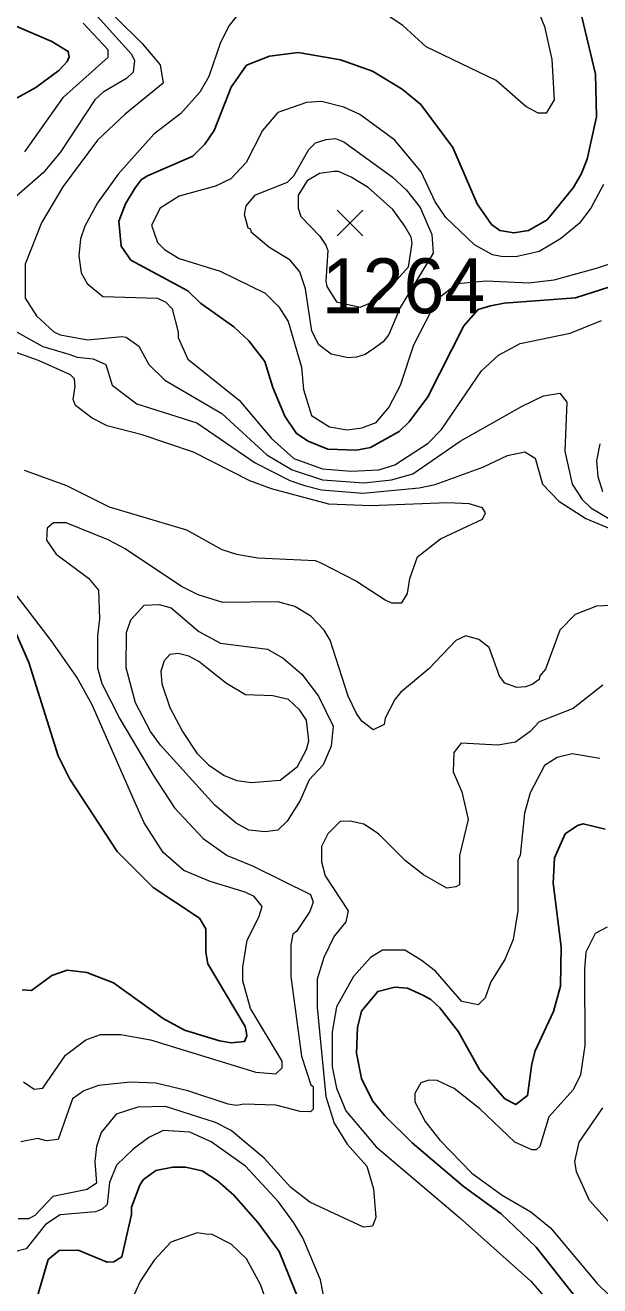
# Model space of a CAD drawing. Extents: x 423 to 448.8, y 7456.3 to 7484.
# Drawn here: x 429.568 to 430.405, y 7470.972 to 7472.809 of the extents above; entities that cross this region are included whole.
import ezdxf
from ezdxf.enums import TextEntityAlignment as Align

# ---------------------------------------------------------------- set-up
doc = ezdxf.new("R2010")
doc.units = 0
doc.header["$LTSCALE"] = 0.032
for name, color, linetype, lineweight in [('1', 7, 'Continuous', 25), ('2', 7, 'Continuous', 13), ('21', 7, 'Continuous', 25)]:
    doc.layers.add(name, color=color, linetype=linetype, lineweight=lineweight)
doc.layers.add('61', color=7, linetype='Continuous')

msp = doc.modelspace()

# ---------------------------------------------------------------- linework, layer by layer
at = {"layer": '1'}
for points in [[(429.5559, 7472.8071), (429.6069, 7472.7854), (429.6309, 7472.7707), (429.6324, 7472.763), (429.6294, 7472.756), (429.617, 7472.7428), (429.5837, 7472.7181), (429.5157, 7472.681)], [(430.1909, 7472.6307), (430.2265, 7472.5487), (430.2473, 7472.5186), (430.2597, 7472.51), (430.2799, 7472.5062), (430.3015, 7472.51), (430.3286, 7472.5255), (430.3665, 7472.5719), (430.3781, 7472.592), (430.3866, 7472.6137), (430.4005, 7472.6756), (430.399, 7472.7375), (430.3788, 7472.821)], [(430.532, 7472.4636), (430.3696, 7472.4118), (430.2659, 7472.4041), (430.2458, 7472.4002), (430.228, 7472.3948), (430.2071, 7472.3708), (430.1545, 7472.2672), (430.1274, 7472.2308), (430.1128, 7472.2169), (430.071, 7472.1937), (430.0509, 7472.1898), (430.0091, 7472.1914), (429.9805, 7472.203), (429.9635, 7472.2138), (429.9465, 7472.2394), (429.9287, 7472.2811), (429.9171, 7472.319), (429.8939, 7472.3492), (429.8722, 7472.3693), (429.8235, 7472.4041), (429.805, 7472.4219), (429.7222, 7472.4667), (429.7082, 7472.4869), (429.7044, 7472.5232), (429.7144, 7472.5487), (429.7283, 7472.5719), (429.7376, 7472.5843), (429.7462, 7472.5897), (429.8126, 7472.6183), (429.8297, 7472.6354), (429.8436, 7472.6555), (429.8684, 7472.7189), (429.8908, 7472.7506), (429.9241, 7472.7637), (429.9658, 7472.7692), (430.0277, 7472.7583), (430.0741, 7472.7421), (430.1174, 7472.7158), (430.1445, 7472.6933), (430.1909, 7472.6307)], [(429.5512, 7471.9315), (429.5737, 7471.8805), (429.6162, 7471.7443), (429.6332, 7471.7103), (429.702, 7471.6051), (429.7547, 7471.5525), (429.8219, 7471.5076), (429.8312, 7471.4922), (429.8312, 7471.4582), (429.8343, 7471.4411), (429.8885, 7471.3499), (429.89, 7471.3429), (429.891, 7471.3362), (429.8877, 7471.3282), (429.8684, 7471.3259), (429.8514, 7471.329), (429.8003, 7471.3444), (429.7694, 7471.3614), (429.6966, 7471.4133), (429.658, 7471.4288), (429.6294, 7471.4318), (429.6069, 7471.4241), (429.5776, 7471.4024), (429.5636, 7471.4032)], [(430.0919, 7471.2199), (430.0741, 7471.2416), (430.0579, 7471.2741), (430.0509, 7471.3112), (430.0524, 7471.3483), (430.0579, 7471.3723), (430.0818, 7471.4009), (430.1066, 7471.4071), (430.1252, 7471.4055), (430.1476, 7471.3955), (430.1592, 7471.3893), (430.1723, 7471.3769), (430.1994, 7471.3421), (430.2303, 7471.2864), (430.2667, 7471.2447), (430.2829, 7471.2361), (430.2999, 7471.2493), (430.3061, 7471.2957), (430.3108, 7471.3143), (430.3378, 7471.3715), (430.3479, 7471.4087), (430.3487, 7471.4659), (430.3371, 7471.5587), (430.3394, 7471.5958), (430.3549, 7471.6306), (430.3727, 7471.643), (430.3811, 7471.6453), (430.4129, 7471.6376)], [(430.3904, 7470.9299), (430.3123, 7471.0281), (430.2613, 7471.0768), (430.2063, 7471.117), (430.1321, 7471.1804), (430.0919, 7471.2199)], [(429.5845, 7470.9523), (429.6015, 7471.0103), (429.6178, 7471.0235), (429.6456, 7471.0242), (429.6874, 7471.0064), (429.6974, 7471.0072), (429.709, 7471.0141), (429.723, 7471.0761), (429.723, 7471.0868), (429.7353, 7471.1186), (429.7381, 7471.1237), (429.7407, 7471.1271), (429.7585, 7471.1402), (429.7833, 7471.1449), (429.8019, 7471.1449), (429.8258, 7471.1395), (429.8483, 7471.1248), (429.8722, 7471.1039), (429.9078, 7471.0637), (429.938, 7471.0219), (429.9681, 7470.9477)]]:
    msp.add_lwpolyline(points, dxfattribs=at)
at = {"layer": '2'}
for points in [[(430.2969, 7472.8751), (430.3247, 7472.8071), (430.3355, 7472.7591), (430.3386, 7472.7003), (430.327, 7472.681), (430.3154, 7472.681), (430.2976, 7472.6903), (430.2543, 7472.7282), (430.1522, 7472.7776), (430.1182, 7472.8086), (430.0865, 7472.8295)], [(429.6626, 7472.8581), (429.7384, 7472.7823), (429.7647, 7472.7514), (429.7694, 7472.7243), (429.7137, 7472.6794), (429.6734, 7472.6415), (429.6232, 7472.5735), (429.5922, 7472.5209), (429.5683, 7472.4606), (429.5683, 7472.4111), (429.5845, 7472.3855), (429.61, 7472.3623), (429.6193, 7472.3577), (429.6595, 7472.3507), (429.709, 7472.3554), (429.7152, 7472.3546), (429.7338, 7472.3414), (429.7485, 7472.3143), (429.7717, 7472.2919), (429.8544, 7472.2432), (429.9202, 7472.1829), (429.9573, 7472.1612), (430.0014, 7472.1465), (430.0617, 7472.1419), (430.102, 7472.1465), (430.1329, 7472.155), (430.2017, 7472.203), (430.2922, 7472.254), (430.3232, 7472.2687), (430.3471, 7472.2726), (430.3572, 7472.2595), (430.3541, 7472.1883), (430.3649, 7472.1403), (430.3796, 7472.1179), (430.392, 7472.1055), (430.4183, 7472.09)], [(429.6688, 7472.8272), (429.7229, 7472.7668), (429.7276, 7472.7576), (429.7253, 7472.7405), (429.716, 7472.7313), (429.6819, 7472.7112), (429.6696, 7472.7003), (429.6193, 7472.6237), (429.5946, 7472.5936)], [(429.8854, 7472.8333), (429.8653, 7472.8086), (429.8529, 7472.7839), (429.8359, 7472.7344), (429.8227, 7472.7112), (429.7949, 7472.6802), (429.7554, 7472.65), (429.7036, 7472.592), (429.6735, 7472.5503), (429.6549, 7472.5162), (429.6487, 7472.4977), (429.6464, 7472.4729), (429.6495, 7472.4482), (429.6587, 7472.4327), (429.6812, 7472.4134), (429.7608, 7472.4111), (429.7732, 7472.4056), (429.7825, 7472.3956), (429.791, 7472.3616), (429.791, 7472.3538), (429.8049, 7472.3221), (429.88, 7472.2625), (429.9271, 7472.2069), (429.9596, 7472.1774), (430.0014, 7472.1627), (430.0432, 7472.1589), (430.0834, 7472.1612), (430.1066, 7472.1682), (430.1553, 7472.1999), (430.1747, 7472.22), (430.2327, 7472.3051), (430.2574, 7472.3283), (430.2891, 7472.3453), (430.3618, 7472.36), (430.4075, 7472.3786)], [(429.5675, 7472.6245), (429.624, 7472.7042), (429.6889, 7472.7622), (429.6889, 7472.773), (429.6526, 7472.8117)], [(430.4105, 7472.5766), (430.392, 7472.5425), (430.375, 7472.5201), (430.3479, 7472.4976), (430.317, 7472.4791), (430.283, 7472.4714), (430.2613, 7472.4721), (430.2489, 7472.4745), (430.2226, 7472.4891), (430.1808, 7472.5286), (430.1653, 7472.5518), (430.1452, 7472.5951), (430.1066, 7472.6415), (430.0556, 7472.6787), (430.0324, 7472.6895), (429.9999, 7472.698), (429.9782, 7472.6964), (429.9364, 7472.6818), (429.914, 7472.6555), (429.89, 7472.609), (429.8676, 7472.5851), (429.8452, 7472.5742), (429.7926, 7472.5596), (429.7647, 7472.5425), (429.7524, 7472.5178), (429.7608, 7472.4922), (429.7709, 7472.4822), (429.7926, 7472.469), (429.8521, 7472.4505), (429.9178, 7472.4187), (429.9379, 7472.3987), (429.9511, 7472.377), (429.9705, 7472.3105), (429.9736, 7472.278), (429.9851, 7472.2401), (430.0114, 7472.2238), (430.037, 7472.2192), (430.0586, 7472.2223), (430.0795, 7472.23), (430.0981, 7472.2517), (430.1151, 7472.2842), (430.1344, 7472.343), (430.169, 7472.41), (430.1976, 7472.4325), (430.2396, 7472.4366), (430.3015, 7472.4335), (430.3386, 7472.4381), (430.4005, 7472.4551), (430.5188, 7472.4938)], [(429.5946, 7472.5936), (429.5218, 7472.5309)], [(429.5512, 7472.3646), (429.5938, 7472.3406), (429.6317, 7472.3298), (429.6441, 7472.3252), (429.6673, 7472.3229), (429.6858, 7472.3144), (429.6951, 7472.2842), (429.7307, 7472.2571), (429.8181, 7472.2293), (429.9032, 7472.1712), (429.9535, 7472.1457), (429.9751, 7472.138), (429.9999, 7472.1318), (430.0602, 7472.1272), (430.1422, 7472.1349), (430.1654, 7472.1395), (430.235, 7472.1651), (430.2706, 7472.1821), (430.2961, 7472.1875), (430.3108, 7472.1782), (430.3216, 7472.1403), (430.3456, 7472.1156), (430.385, 7472.09), (430.4686, 7472.0553)], [(429.6286, 7472.138), (429.6905, 7472.1071), (429.8034, 7472.0738), (429.8545, 7472.0452), (429.8761, 7472.0382), (429.9071, 7472.0328), (429.9906, 7472.029), (429.9999, 7472.0251), (430.0509, 7471.9988), (430.0927, 7471.9717), (430.102, 7471.9671), (430.1166, 7471.9671), (430.1252, 7471.981), (430.1283, 7472.0027), (430.1398, 7472.0344), (430.1731, 7472.0606), (430.2342, 7472.0893), (430.2388, 7472.0986), (430.2342, 7472.1055), (430.2149, 7472.1117), (430.1839, 7472.1132), (430.071, 7472.1086), (430.0107, 7472.1109), (429.9272, 7472.1334), (429.8954, 7472.145), (429.8134, 7472.1867), (429.7384, 7472.2122), (429.6874, 7472.2254), (429.6657, 7472.2363), (429.6417, 7472.2548), (429.6379, 7472.2633), (429.641, 7472.2827), (429.6402, 7472.2935), (429.634, 7472.2997), (429.5876, 7472.3205), (429.5234, 7472.343)], [(430.4052, 7472.1991), (430.4005, 7472.1744), (430.4021, 7472.1512), (430.409, 7472.1295)], [(429.5667, 7472.1605), (429.6286, 7472.138)], [(429.7137, 7472.0459), (429.6889, 7472.0591), (429.6278, 7472.0839), (429.6092, 7472.0839), (429.6, 7472.0761), (429.5992, 7472.0584), (429.6131, 7472.0382), (429.6603, 7472.0034), (429.675, 7471.9857), (429.6766, 7471.9439), (429.6735, 7471.9191), (429.6735, 7471.8727), (429.6796, 7471.8495), (429.7059, 7471.7984), (429.7554, 7471.7149), (429.7856, 7471.6685), (429.8274, 7471.6237), (429.8622, 7471.5989), (429.8993, 7471.5842), (429.9836, 7471.5424), (429.9875, 7471.5309), (429.9828, 7471.5177), (429.9635, 7471.4883), (429.9581, 7471.4845), (429.955, 7471.469), (429.955, 7471.4226), (429.9705, 7471.3066), (429.9844, 7471.2648), (429.9875, 7471.2624), (429.9875, 7471.2292), (429.9836, 7471.2253), (429.9689, 7471.2261), (429.9333, 7471.2354), (429.8869, 7471.2369), (429.8761, 7471.2346), (429.8637, 7471.2369), (429.805, 7471.2562), (429.7585, 7471.2671), (429.7214, 7471.2686), (429.675, 7471.264), (429.6534, 7471.2562), (429.6371, 7471.2447), (429.6162, 7471.1851), (429.5992, 7471.1835), (429.5868, 7471.1866), (429.562, 7471.182)], [(429.5659, 7471.2694), (429.5814, 7471.2586), (429.5938, 7471.2601), (429.6271, 7471.3081), (429.6564, 7471.3305), (429.6781, 7471.3382), (429.7075, 7471.3382), (429.7508, 7471.3305), (429.904, 7471.2833), (429.9333, 7471.281), (429.9426, 7471.2895), (429.9426, 7471.2996), (429.8962, 7471.3762), (429.8854, 7471.4164), (429.8854, 7471.4365), (429.8916, 7471.4759), (429.9086, 7471.5092), (429.9132, 7471.5247), (429.9016, 7471.5393), (429.8885, 7471.5455), (429.8374, 7471.561), (429.7995, 7471.5773), (429.7693, 7471.6036), (429.7415, 7471.6469), (429.7268, 7471.6794), (429.6657, 7471.8186), (429.6433, 7471.8588), (429.6061, 7471.9122), (429.5041, 7472.0452)], [(430.4206, 7471.9632), (430.4005, 7471.9624), (430.3695, 7471.9501), (430.3471, 7471.9276), (430.3262, 7471.8704), (430.3177, 7471.8611), (430.3169, 7471.8557), (430.3069, 7471.848), (430.2969, 7471.8449), (430.2845, 7471.8441), (430.2667, 7471.8503), (430.2589, 7471.8604), (430.2442, 7471.9021), (430.2288, 7471.9137), (430.2102, 7471.9191), (430.1955, 7471.9122), (430.1561, 7471.8712), (430.1151, 7471.8364), (430.1066, 7471.8263), (430.0927, 7471.7992), (430.0911, 7471.7899), (430.0749, 7471.7822), (430.0586, 7471.7946), (430.0509, 7471.8062), (430.0385, 7471.831), (430.0122, 7471.913), (430.0037, 7471.9276), (429.9844, 7471.9477), (429.9612, 7471.9617), (429.9364, 7471.9686), (429.856, 7471.9678), (429.8204, 7471.9787), (429.7957, 7471.991), (429.7137, 7472.0459)], [(430.4098, 7471.8472), (430.3665, 7471.8131), (430.317, 7471.7938), (430.3038, 7471.7799), (430.2822, 7471.7644), (430.2567, 7471.7598), (430.2033, 7471.7629), (430.1924, 7471.749), (430.1917, 7471.7211), (430.2041, 7471.6917), (430.2133, 7471.6515), (430.201, 7471.5989), (430.201, 7471.5564), (430.1955, 7471.5533), (430.1824, 7471.5517), (430.1484, 7471.5711), (430.1221, 7471.5911), (430.0826, 7471.6306), (430.0617, 7471.6445), (430.0416, 7471.6492), (430.0269, 7471.6484), (430.0091, 7471.6306), (429.9999, 7471.612), (429.9999, 7471.5896), (430.0052, 7471.5695), (430.0385, 7471.5185), (430.0354, 7471.5022), (430.0184, 7471.4814), (430.003, 7471.4504), (429.9937, 7471.4187), (429.9937, 7471.3777), (430.006, 7471.2478), (430.0184, 7471.2091), (430.037, 7471.1782), (430.0656, 7471.1464), (430.0757, 7471.1132), (430.0788, 7471.0714), (430.0741, 7471.059), (430.0609, 7471.0575), (429.9828, 7471.0938), (429.955, 7471.1155), (429.9163, 7471.158), (429.8683, 7471.1983), (429.8452, 7471.2098), (429.7725, 7471.2331), (429.7322, 7471.2323), (429.7005, 7471.2222), (429.6788, 7471.1952), (429.6719, 7471.1751), (429.6696, 7471.1534), (429.6719, 7471.1217), (429.6587, 7471.1124), (429.6085, 7471.1024), (429.5822, 7471.0745), (429.5729, 7471.0698), (429.5582, 7471.0698)], [(430.4052, 7471.7404), (430.3649, 7471.7474), (430.3433, 7471.742), (430.3247, 7471.7304), (430.3038, 7471.6902), (430.2953, 7471.6608), (430.2891, 7471.5989), (430.286, 7471.5927), (430.286, 7471.5185), (430.2791, 7471.4767)], [(430.416, 7471.4945), (430.3982, 7471.4852), (430.385, 7471.4582), (430.3827, 7471.4334), (430.3835, 7471.322), (430.3773, 7471.2795), (430.3665, 7471.2578), (430.3309, 7471.2183), (430.3177, 7471.175), (430.3123, 7471.1704), (430.3062, 7471.1704), (430.2814, 7471.1812), (430.2304, 7471.23), (430.1932, 7471.2593), (430.1685, 7471.271), (430.1561, 7471.2717), (430.1445, 7471.2678), (430.136, 7471.2524), (430.136, 7471.24), (430.1507, 7471.2114), (430.1723, 7471.1843), (430.2187, 7471.1364), (430.2628, 7471.1039), (430.3046, 7471.0799), (430.3332, 7471.0567), (430.4013, 7470.9755), (430.4376, 7470.9399)], [(430.2791, 7471.4767), (430.2667, 7471.4473), (430.2466, 7471.4148), (430.2381, 7471.3916), (430.228, 7471.3816), (430.2041, 7471.3862), (430.1661, 7471.4303), (430.1452, 7471.4465), (430.1213, 7471.4612), (430.0888, 7471.4612), (430.071, 7471.4504), (430.0462, 7471.4226), (430.0215, 7471.3785), (430.0153, 7471.3421), (430.0153, 7471.2911), (430.0215, 7471.2601), (430.0354, 7471.2269), (430.0795, 7471.1743), (430.201, 7471.0714), (430.3046, 7470.9786), (430.3239, 7470.957)], [(430.4632, 7471.0157), (430.3904, 7471.0962), (430.3711, 7471.1379), (430.3688, 7471.1534), (430.375, 7471.1813), (430.4098, 7471.2315)], [(430.0153, 7470.8935), (429.9983, 7470.9809), (429.9728, 7471.042), (429.9596, 7471.0637), (429.9372, 7471.0946), (429.8892, 7471.1464), (429.839, 7471.182), (429.808, 7471.1959), (429.7694, 7471.1983), (429.7485, 7471.1882), (429.7253, 7471.1712), (429.7013, 7471.148), (429.6912, 7471.1225), (429.6874, 7471.0907), (429.6804, 7471.0838), (429.6704, 7471.0799), (429.6193, 7471.0753), (429.5976, 7471.0613), (429.5698, 7471.0258), (429.5544, 7471.0219)], [(429.924, 7470.9368), (429.9109, 7470.974), (429.8908, 7471.0111), (429.8684, 7471.0327), (429.8405, 7471.0466), (429.8313, 7471.0474), (429.8189, 7471.049), (429.7802, 7471.0358), (429.7562, 7471.0095), (429.7361, 7470.9794), (429.7237, 7470.9523)]]:
    msp.add_lwpolyline(points, dxfattribs=at)
for points in [[(430.0068, 7472.6423), (430.02, 7472.6438), (430.0324, 7472.6392), (430.1027, 7472.5881), (430.1236, 7472.5688), (430.1437, 7472.5433), (430.1607, 7472.5038), (430.1623, 7472.4768), (430.1143, 7472.3974), (430.0981, 7472.3585), (430.0895, 7472.3476), (430.0757, 7472.3375), (430.0633, 7472.3291), (430.0509, 7472.3252), (430.0385, 7472.3244), (430.0138, 7472.3298), (429.996, 7472.343), (429.9859, 7472.3631), (429.9767, 7472.425), (429.9681, 7472.4497), (429.9542, 7472.4667), (429.9233, 7472.4853), (429.8977, 7472.5069), (429.897, 7472.5116), (429.8931, 7472.5131), (429.8877, 7472.5333), (429.89, 7472.5456), (429.9039, 7472.5619), (429.9503, 7472.5804), (429.9596, 7472.5897), (429.9813, 7472.6276), (429.9913, 7472.6377)], [(430.0216, 7472.4058), (430.0561, 7472.3983), (430.0847, 7472.4103), (430.1267, 7472.4567), (430.1321, 7472.4915), (430.1306, 7472.5), (430.1213, 7472.5162), (430.1035, 7472.5402), (430.0679, 7472.5727), (430.0432, 7472.5874), (430.0246, 7472.5959), (430.0184, 7472.5959), (429.9968, 7472.5928), (429.9789, 7472.582), (429.9658, 7472.5611), (429.9658, 7472.5425), (429.9697, 7472.5302), (429.9975, 7472.5015), (430.006, 7472.4884), (430.0091, 7472.4807), (430.006, 7472.4358), (430.0076, 7472.428)], [(429.7415, 7471.9639), (429.7632, 7471.9647), (429.7809, 7471.9601), (429.8212, 7471.9253), (429.8529, 7471.9083), (429.921, 7471.8998), (429.9442, 7471.8866), (429.9712, 7471.8634), (429.9952, 7471.831), (430.0169, 7471.7876), (430.0138, 7471.7583), (430.0022, 7471.7312), (429.982, 7471.7095), (429.9689, 7471.6794), (429.9496, 7471.6492), (429.9364, 7471.636), (429.9179, 7471.6337), (429.8939, 7471.636), (429.8753, 7471.6461), (429.8444, 7471.6724), (429.7655, 7471.7598), (429.7508, 7471.7799), (429.7291, 7471.8217), (429.7152, 7471.8727), (429.716, 7471.9238), (429.7222, 7471.9423)], [(429.8978, 7471.7056), (429.9395, 7471.7087), (429.965, 7471.7288), (429.9782, 7471.7536), (429.9813, 7471.766), (429.9782, 7471.7961), (429.9681, 7471.8109), (429.9519, 7471.8263), (429.9287, 7471.8317), (429.8892, 7471.8333), (429.8614, 7471.8495), (429.8335, 7471.8719), (429.8212, 7471.8819), (429.8064, 7471.8897), (429.7908, 7471.8936), (429.7791, 7471.8921), (429.7705, 7471.8827), (429.7659, 7471.8678), (429.7674, 7471.8491), (429.7791, 7471.8147), (429.7971, 7471.7796), (429.8181, 7471.7484), (429.8353, 7471.7312), (429.8579, 7471.7156), (429.8766, 7471.7085)]]:
    msp.add_lwpolyline(points, close=True, dxfattribs=at)
at = {"layer": '21'}
for p, q in [((430.0227, 7472.5394), (430.0602, 7472.5019)), ((430.0602, 7472.5394), (430.0227, 7472.5019))]:
    msp.add_line(p, q, dxfattribs=at)

# ---------------------------------------------------------------- texts
at = {"layer": '61'}
msp.add_text('1264', height=0.08, dxfattribs=at).set_placement((430.1193, 7472.3892), align=Align.CENTER)

doc.saveas('drawing.dxf')
